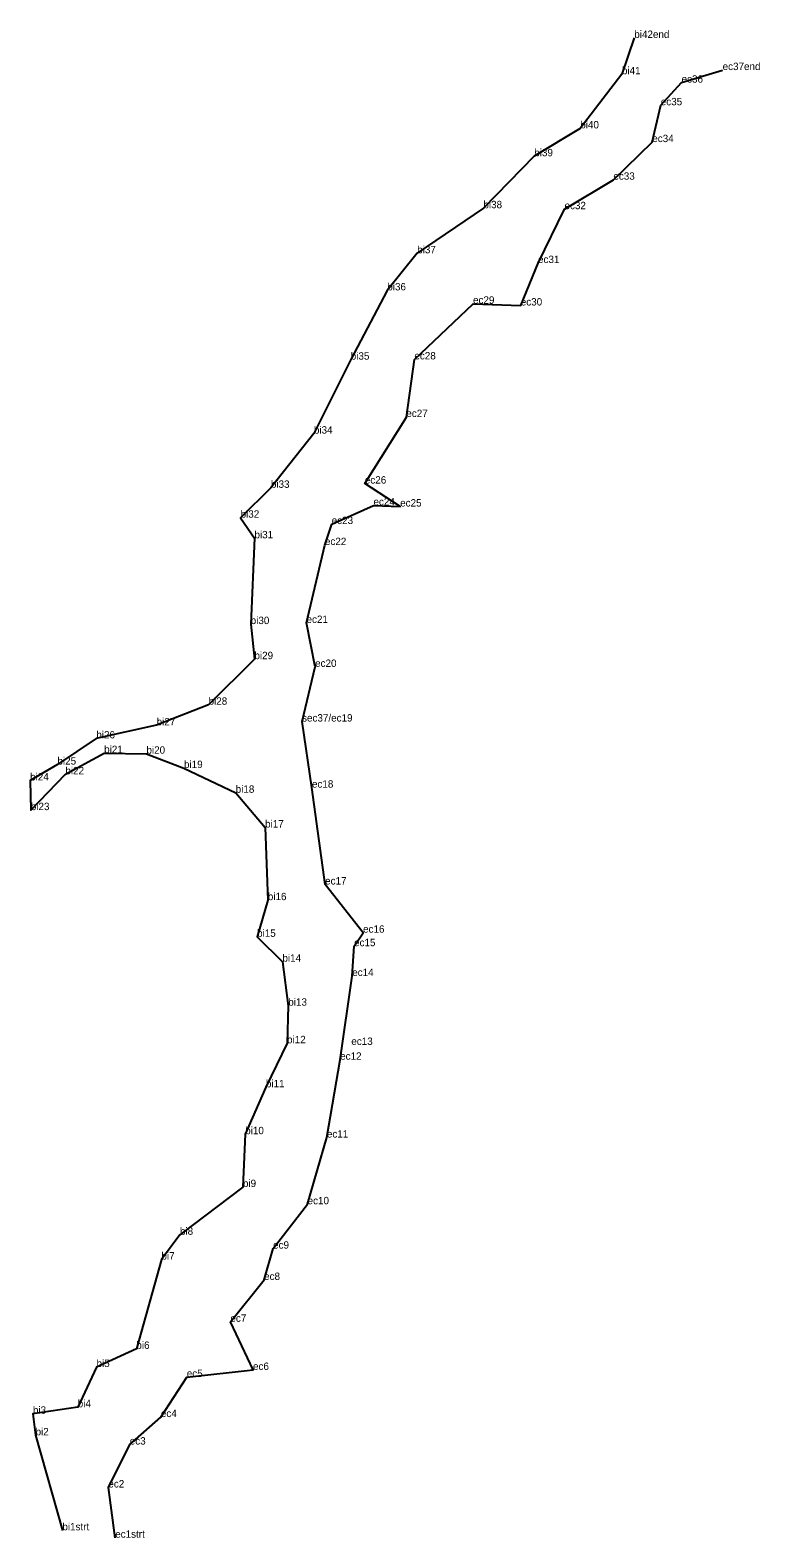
# Model space of a CAD drawing. Extents: x 2072529 to 2267990, y 436423 to 470008.
# Drawn here: x 2218503 to 2219096, y 437904 to 439129 of the extents above; entities that cross this region are included whole.
import ezdxf

# ---------------------------------------------------------------- set-up
doc = ezdxf.new("R2010")
doc.units = 0
doc.layers.add('Level 3', color=7, linetype='Continuous')
doc.layers.add('Old_Level_52', color=7, linetype='Continuous')

msp = doc.modelspace()

# ---------------------------------------------------------------- linework, layer by layer
at = {"layer": 'Level 3'}
for p, q in [((2218994.124, 439122.965), (2218994.124, 439122.965)), ((2218984.074, 439093.453), (2218984.074, 439093.453)), ((2219065.951, 439096.83), (2219065.951, 439096.83)), ((2219032.592, 439086.617), (2219032.592, 439086.617)), ((2219015.662, 439068.204), (2219015.662, 439068.204)), ((2218950.191, 439049.408), (2218950.191, 439049.408)), ((2219008.764, 439038.272), (2219008.764, 439038.272)), ((2218912.795, 439026.758), (2218912.795, 439026.758)), ((2218977.121, 439007.679), (2218977.121, 439007.679)), ((2218871.442, 438984.518), (2218871.442, 438984.518)), ((2218937.399, 438983.731), (2218937.399, 438983.731)), ((2218817.598, 438947.868), (2218817.598, 438947.868)), ((2218915.844, 438939.949), (2218915.844, 438939.949)), ((2218793.284, 438917.698), (2218793.284, 438917.698)), ((2218863.006, 438906.918), (2218863.006, 438906.918)), ((2218901.83, 438905.432), (2218901.83, 438905.432)), ((2218763.563, 438861.424), (2218763.563, 438861.424)), ((2218815.326, 438861.596), (2218815.326, 438861.596)), ((2218808.776, 438814.765), (2218808.776, 438814.765)), ((2218733.615, 438801.271), (2218733.615, 438801.271)), ((2218775.039, 438760.657), (2218775.039, 438760.657)), ((2218698.633, 438757.209), (2218698.633, 438757.209)), ((2218782.055, 438742.91), (2218782.055, 438742.91)), ((2218803.751, 438741.995), (2218803.751, 438741.995)), ((2218674.021, 438732.917), (2218674.021, 438732.917)), ((2218748.068, 438727.741), (2218748.068, 438727.741)), ((2218685.306, 438716.175), (2218685.306, 438716.175)), ((2218742.581, 438710.677), (2218742.581, 438710.677)), ((2218682.216, 438646.424), (2218682.216, 438646.424)), ((2218727.636, 438647.342), (2218727.636, 438647.342)), ((2218685.264, 438617.909), (2218685.264, 438617.909)), ((2218734.593, 438611.632), (2218734.593, 438611.632)), ((2218647.963, 438580.864), (2218647.963, 438580.864)), ((2218605.754, 438564.129), (2218605.754, 438564.129)), ((2218723.993, 438567.188), (2218723.993, 438567.188)), ((2218556.681, 438553.468), (2218556.681, 438553.468)), ((2218563.066, 438541.56), (2218563.066, 438541.56)), ((2218597.462, 438541.071), (2218597.462, 438541.071)), ((2218525.105, 438532.197), (2218525.105, 438532.197)), ((2218627.985, 438529.398), (2218627.985, 438529.398)), ((2218502.89, 438519.272), (2218502.89, 438519.272)), ((2218531.556, 438524.3), (2218531.556, 438524.3)), ((2218670.025, 438509.286), (2218670.025, 438509.286)), ((2218732.037, 438513.467), (2218732.037, 438513.467)), ((2218503.431, 438495.183), (2218503.431, 438495.183)), ((2218693.909, 438481.037), (2218693.909, 438481.037)), ((2218742.73, 438434.703), (2218742.73, 438434.703)), ((2218696.143, 438421.987), (2218696.143, 438421.987)), ((2218687.424, 438392.189), (2218687.424, 438392.189)), ((2218773.596, 438395.526), (2218773.596, 438395.526)), ((2218766.27, 438384.548), (2218766.27, 438384.548)), ((2218708.026, 438371.959), (2218708.026, 438371.959)), ((2218764.788, 438360.305), (2218764.788, 438360.305)), ((2218712.78, 438336.2), (2218712.78, 438336.2)), ((2218711.767, 438305.673), (2218711.767, 438305.673)), ((2218764.027, 438304.308), (2218764.027, 438304.308)), ((2218754.942, 438292.25), (2218754.942, 438292.25)), ((2218694.582, 438269.871), (2218694.582, 438269.871)), ((2218677.732, 438231.72), (2218677.732, 438231.72)), ((2218744.177, 438228.991), (2218744.177, 438228.991)), ((2218675.911, 438188.771), (2218675.911, 438188.771)), ((2218728.483, 438174.772), (2218728.483, 438174.772)), ((2218624.699, 438149.937), (2218624.699, 438149.937)), ((2218700.445, 438138.681), (2218700.445, 438138.681)), ((2218609.622, 438129.816), (2218609.622, 438129.816)), ((2218693.127, 438113.216), (2218693.127, 438113.216)), ((2218665.752, 438079.193), (2218665.752, 438079.193)), ((2218589.251, 438057.208), (2218589.251, 438057.208)), ((2218556.845, 438042.41), (2218556.845, 438042.41)), ((2218684.093, 438040.085), (2218684.093, 438040.085)), ((2218630.248, 438034.278), (2218630.248, 438034.278)), ((2218505.157, 438004.448), (2218505.157, 438004.448)), ((2218541.587, 438009.767), (2218541.587, 438009.767)), ((2218609.184, 438001.731), (2218609.184, 438001.731)), ((2218507.315, 437986.909), (2218507.315, 437986.909)), ((2218583.896, 437979.396), (2218583.896, 437979.396)), ((2218566.496, 437944.492), (2218566.496, 437944.492)), ((2218529.104, 437909.666), (2218529.104, 437909.666)), ((2218572.059, 437903.647), (2218572.059, 437903.647))]:
    msp.add_line(p, q, dxfattribs=at)
at = {"layer": 'Old_Level_52'}
for points in [[(2218994.124, 439122.965), (2218984.074, 439093.453), (2218950.191, 439049.408), (2218912.795, 439026.758), (2218871.442, 438984.518), (2218817.598, 438947.868), (2218793.284, 438917.698), (2218763.563, 438861.424), (2218733.615, 438801.271), (2218698.633, 438757.209), (2218674.021, 438732.917), (2218685.306, 438716.175), (2218682.216, 438646.424), (2218685.264, 438617.909), (2218647.963, 438580.864), (2218605.754, 438564.129), (2218556.681, 438553.468), (2218525.105, 438532.197), (2218502.89, 438519.272), (2218503.431, 438495.183), (2218531.556, 438524.3), (2218563.066, 438541.56), (2218597.462, 438541.071), (2218627.985, 438529.398), (2218670.025, 438509.286), (2218693.909, 438481.037), (2218696.143, 438421.987), (2218687.424, 438392.189), (2218708.026, 438371.959), (2218712.78, 438336.2), (2218711.767, 438305.673), (2218694.582, 438269.871), (2218677.732, 438231.72), (2218675.911, 438188.771), (2218624.699, 438149.937), (2218609.622, 438129.816), (2218589.251, 438057.208), (2218556.845, 438042.41), (2218541.587, 438009.767), (2218505.157, 438004.448), (2218507.315, 437986.909), (2218529.104, 437909.666)], [(2218572.059, 437903.647), (2218566.496, 437944.492), (2218583.896, 437979.396), (2218609.184, 438001.731), (2218630.248, 438034.278), (2218684.093, 438040.085), (2218665.752, 438079.193), (2218693.127, 438113.216), (2218700.445, 438138.681), (2218728.483, 438174.772), (2218744.177, 438228.991), (2218754.942, 438292.25), (2218764.788, 438360.305), (2218766.27, 438384.548), (2218773.596, 438395.526), (2218742.73, 438434.703), (2218732.037, 438513.467), (2218723.993, 438567.188), (2218734.593, 438611.632), (2218727.636, 438647.342), (2218742.581, 438710.677), (2218748.068, 438727.741), (2218782.055, 438742.91), (2218803.751, 438741.995), (2218775.039, 438760.657), (2218808.776, 438814.765), (2218815.326, 438861.596), (2218863.006, 438906.918), (2218901.83, 438905.432), (2218915.844, 438939.949), (2218937.399, 438983.731), (2218977.121, 439007.679), (2219008.764, 439038.272), (2219015.662, 439068.204), (2219032.592, 439086.617), (2219065.951, 439096.83)]]:
    msp.add_lwpolyline(points, dxfattribs=at)

# ---------------------------------------------------------------- texts
for s, p in [('bi42end', (2218994.124, 439122.965)), ('ec37end', (2219065.951, 439096.83)), ('bi41', (2218984.074, 439093.453)), ('ec36', (2219032.592, 439086.617)), ('ec35', (2219015.662, 439068.204)), ('bi40', (2218950.191, 439049.408)), ('ec34', (2219008.764, 439038.272)), ('bi39', (2218912.795, 439026.758)), ('ec33', (2218977.121, 439007.679)), ('bi38', (2218871.442, 438984.518)), ('ec32', (2218937.399, 438983.731)), ('bi37', (2218817.598, 438947.868)), ('ec31', (2218915.844, 438939.949)), ('bi36', (2218793.284, 438917.698)), ('ec29', (2218863.006, 438906.918)), ('ec30', (2218901.83, 438905.432)), ('bi35', (2218763.563, 438861.424)), ('ec28', (2218815.326, 438861.596)), ('ec27', (2218808.776, 438814.765)), ('bi34', (2218733.615, 438801.271)), ('bi33', (2218698.633, 438757.209)), ('ec26', (2218775.039, 438760.657)), ('ec24', (2218782.055, 438742.91)), ('ec25', (2218803.751, 438741.995)), ('bi32', (2218674.021, 438732.917)), ('ec23', (2218748.068, 438727.741)), ('bi31', (2218685.306, 438716.175)), ('ec22', (2218742.581, 438710.677)), ('bi30', (2218682.216, 438646.424)), ('ec21', (2218727.636, 438647.342)), ('bi29', (2218685.264, 438617.909)), ('ec20', (2218734.593, 438611.632)), ('bi28', (2218647.963, 438580.864)), ('bi27', (2218605.754, 438564.129)), ('sec37/ec19', (2218723.993, 438567.188)), ('bi26', (2218556.681, 438553.468)), ('bi21', (2218563.066, 438541.56)), ('bi20', (2218597.462, 438541.071)), ('bi25', (2218525.105, 438532.197)), ('bi22', (2218531.556, 438524.3)), ('bi19', (2218627.985, 438529.398)), ('bi24', (2218502.89, 438519.272)), ('bi18', (2218670.025, 438509.286)), ('ec18', (2218732.037, 438513.467)), ('bi23', (2218503.431, 438495.183)), ('bi17', (2218693.909, 438481.037)), ('ec17', (2218742.73, 438434.703)), ('bi16', (2218696.143, 438421.987)), ('bi15', (2218687.424, 438392.189)), ('ec16', (2218773.596, 438395.526)), ('ec15', (2218766.27, 438384.548)), ('bi14', (2218708.026, 438371.959)), ('ec14', (2218764.788, 438360.305)), ('bi13', (2218712.78, 438336.2)), ('bi12', (2218711.767, 438305.673)), ('ec13', (2218764.027, 438304.308)), ('ec12', (2218754.942, 438292.25)), ('bi11', (2218694.582, 438269.871)), ('bi10', (2218677.732, 438231.72)), ('ec11', (2218744.177, 438228.991)), ('bi9', (2218675.911, 438188.771)), ('ec10', (2218728.483, 438174.772)), ('bi8', (2218624.699, 438149.937)), ('bi7', (2218609.622, 438129.816)), ('ec9', (2218700.445, 438138.681)), ('ec8', (2218693.127, 438113.216)), ('ec7', (2218665.752, 438079.193)), ('bi6', (2218589.251, 438057.208)), ('bi5', (2218556.845, 438042.41)), ('ec5', (2218630.248, 438034.278)), ('ec6', (2218684.093, 438040.085)), ('bi4', (2218541.587, 438009.767)), ('bi3', (2218505.157, 438004.448)), ('ec4', (2218609.184, 438001.731)), ('bi2', (2218507.315, 437986.909)), ('ec3', (2218583.896, 437979.396)), ('ec2', (2218566.496, 437944.492)), ('bi1strt', (2218529.104, 437909.666)), ('ec1strt', (2218572.059, 437903.647))]:
    msp.add_text(s, height=6).set_placement(p)

doc.saveas('drawing.dxf')
